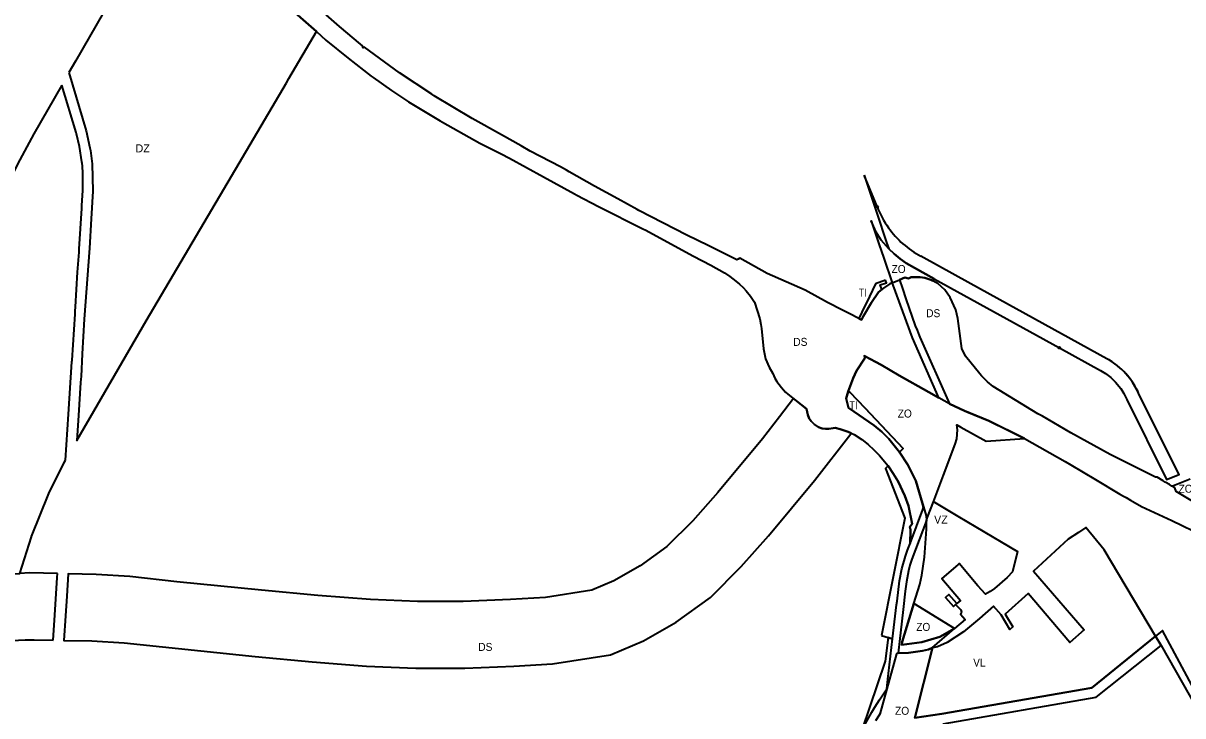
# Model space of a CAD drawing. Extents: x -650276 to -642489, y -1074311 to -1066658.
# Drawn here: x -647860 to -646121, y -1069166 to -1068126 of the extents above; entities that cross this region are included whole.
import ezdxf

# ---------------------------------------------------------------- set-up
doc = ezdxf.new("R2010")
doc.units = 0
doc.header["$LTSCALE"] = 4.8
doc.header["$PDMODE"] = 32
doc.header["$PDSIZE"] = 2.4
for name, color, linetype, lineweight in [('15', 7, 'Continuous', 35), ('24', 7, 'Continuous', 35), ('25', 7, 'Continuous', 35), ('30', 7, 'Continuous', 35), ('34', 7, 'Continuous', 35), ('36', 7, 'Continuous', 35), ('42', 7, 'Continuous', 35)]:
    doc.layers.add(name, color=color, linetype=linetype, lineweight=lineweight)
doc.layers.add('62', color=7, linetype='Continuous')

msp = doc.modelspace()

# ---------------------------------------------------------------- linework, layer by layer
at = {"layer": '15'}
msp.add_lwpolyline([(-646037.99, -1069242.88), (-646107, -1069119.41), (-646150.87, -1069037.64), (-646152.26, -1069038.76), (-646161.484, -1069046.228), (-646153.307, -1069059.947), (-646025.14, -1069285.394)], dxfattribs=at)
at = {"layer": '24'}
msp.add_line((-646578.881, -1068401.54), (-646598.635, -1068354.436), dxfattribs=at)
msp.add_line((-646578.881, -1068401.54), (-646598.635, -1068354.436), dxfattribs=at)
for points in [[(-647618.773, -1067899.914), (-647553.628, -1067999.427), (-647472.338, -1068093.096), (-647419.713, -1068138.871)], [(-646634.37, -1068735.27), (-646622.62, -1068739.32), (-646613.44, -1068743.65), (-646601.86, -1068751.01), (-646592.53, -1068758.66), (-646583.98, -1068766.42), (-646575.28, -1068775.04), (-646562.49, -1068790.69), (-646554.8, -1068801.98), (-646547.68, -1068814.22), (-646537.35, -1068835.56), (-646532.16, -1068850.47), (-646526.64, -1068877.47), (-646530.06, -1068882.16), (-646528.92, -1068886.55), (-646529.44, -1068906.81), (-646510.56, -1068855.86), (-646509.323, -1068852.529), (-646513.27, -1068838.37), (-646521.18, -1068812.95), (-646532.92, -1068788.95), (-646545.32, -1068769.89), (-646561.5, -1068750.22), (-646571.91, -1068739.54), (-646583.49, -1068729.76), (-646622.01, -1068703.3), (-646625.35, -1068689.7), (-646622.68, -1068678.75), (-646615.19, -1068659.11), (-646609.7, -1068647.84), (-646597.4, -1068628.74), (-646596.28, -1068626.52), (-646596.28, -1068626.52), (-646573.14, -1068638.98), (-646545.73, -1068654.81), (-646545.73, -1068654.81), (-646501.64, -1068679.81), (-646486.23, -1068688.54), (-646526.1, -1068598.55), (-646555, -1068519.38), (-646555, -1068519.38), (-646556.22, -1068515.84), (-646559.72, -1068517.29), (-646569.61, -1068524.1), (-646572.02, -1068526.07), (-646577.07, -1068530.2), (-646587.28, -1068545.28), (-646599.75, -1068566.49), (-646602.21, -1068571.5), (-646606.59, -1068569.33), (-646620.94, -1068561.96), (-646625.86, -1068559.47), (-646631.18, -1068556.77), (-646653.21, -1068545.58), (-646686.84, -1068526.89), (-646686.84, -1068526.89), (-646743.69, -1068501.76), (-646785.05, -1068479.12), (-646787.55, -1068480.36), (-646789.49, -1068481.31), (-646832.29, -1068460.04), (-646864.48, -1068444.64), (-646936.47, -1068407.23), (-646938.95, -1068405.8), (-646967.64, -1068390), (-647002.71, -1068371.09), (-647040.77, -1068349.4), (-647044.93, -1068347.08), (-647053.75, -1068342.11), (-647099.2, -1068318.27), (-647112.813, -1068310.564), (-647142.41, -1068293.81), (-647186.26, -1068269.45), (-647243.39, -1068235.26), (-647246.8, -1068233.08), (-647295.47, -1068201.09), (-647347.74, -1068162.54), (-647349.59, -1068163.24), (-647350.6, -1068160.26), (-647353.81, -1068157.67), (-647385.13, -1068131.51), (-647405.026, -1068113.904)], [(-647419.713, -1068138.871), (-647405.71, -1068151.74), (-647372.38, -1068179.01), (-647337.74, -1068205.67), (-647334.62, -1068208.02), (-647307.39, -1068227.44), (-647281.64, -1068244.34), (-647234.11, -1068273.04), (-647230.83, -1068274.93), (-647174.56, -1068306.35), (-647142.788, -1068322.462), (-647130.29, -1068328.8), (-647079.16, -1068357.01), (-647032.91, -1068382.51), (-647029.23, -1068384.46), (-646997.06, -1068401.37), (-646929.56, -1068435.42), (-646927.06, -1068436.66)], [(-646598.635, -1068354.436), (-646579.62, -1068411.29), (-646564.78, -1068455.41), (-646561.544, -1068464.842)], [(-646598.635, -1068354.436), (-646579.62, -1068411.29), (-646564.78, -1068455.41), (-646561.544, -1068464.842)], [(-646927.06, -1068436.66), (-646854.18, -1068475.8), (-646828.2, -1068489.61), (-646807.82, -1068501.17), (-646799.79, -1068506.39), (-646790.66, -1068513.24), (-646785.34, -1068517.77), (-646779.93, -1068522.9), (-646775.44, -1068527.74), (-646768.95, -1068535.8), (-646763.1, -1068545.18), (-646754.92, -1068569.81), (-646753.35, -1068578.6), (-646752.59, -1068584.55), (-646749.35, -1068615.18), (-646746.32, -1068630.23), (-646740.91, -1068642.34), (-646735.62, -1068652.21), (-646732.25, -1068659.06), (-646729.34, -1068663.94), (-646722.6, -1068673.11), (-646716.39, -1068679.8), (-646716.39, -1068679.8), (-646712.93, -1068683), (-646684.7, -1068704.95), (-646682.98, -1068714.07), (-646680.88, -1068719.28), (-646678.08, -1068723.7), (-646673.16, -1068728.69), (-646667.17, -1068732.38), (-646667.17, -1068732.38), (-646661.5, -1068734.35), (-646656.47, -1068735.13), (-646651.21, -1068734.99), (-646645.18, -1068733.91), (-646642.04, -1068733.74), (-646634.37, -1068735.27)], [(-646561.544, -1068464.842), (-646553.677, -1068472.283), (-646544.525, -1068479.79), (-646535.245, -1068486.342), (-646523.105, -1068493.54), (-646493.511, -1068509.855), (-646305.678, -1068613.404)], [(-646561.544, -1068464.842), (-646553.677, -1068472.283), (-646544.525, -1068479.79), (-646535.245, -1068486.342), (-646523.105, -1068493.54), (-646493.511, -1068509.855), (-646305.678, -1068613.404)], [(-646234.342, -1068629.893), (-646234.342, -1068629.892), (-646438.626, -1068517.274), (-646513.45, -1068476.025), (-646513.567, -1068475.963)], [(-646234.342, -1068629.893), (-646234.342, -1068629.892), (-646438.626, -1068517.274), (-646513.45, -1068476.025), (-646513.567, -1068475.963)], [(-646337.93, -1068712.4), (-646404.83, -1068671.52), (-646413.45, -1068664.71), (-646422.32, -1068655.58), (-646425.11, -1068652.37), (-646446.54, -1068626.14), (-646451.82, -1068614.31), (-646458.03, -1068569.26), (-646461.14, -1068556.34), (-646469.51, -1068538.15), (-646477.41, -1068526.45), (-646487.92, -1068516.87), (-646498.48, -1068511.26), (-646507.4, -1068508.45), (-646514.39, -1068507.56), (-646528.18, -1068507.58), (-646531.9, -1068509.25), (-646537.71, -1068508.16), (-646545.57, -1068511.42), (-646541.06, -1068524.58), (-646535.84, -1068539.8), (-646521.81, -1068580.69), (-646519.14, -1068587.06), (-646516.07, -1068595.08), (-646515.09, -1068597.29), (-646470.65, -1068697.38), (-646448.02, -1068707.99), (-646444.51, -1068709.64), (-646411.3, -1068723.11), (-646380.94, -1068737.81), (-646357.87, -1068749.64), (-646297.08, -1068783.8), (-646288.37, -1068789.04), (-646251.73, -1068811.04), (-646214.92, -1068832.85), (-646208.7, -1068836.39), (-646205.48, -1068838.23), (-646199.24, -1068841.79), (-646195.52, -1068843.92), (-646182.57, -1068851.3)], [(-646305.678, -1068613.404), (-646243.997, -1068647.407), (-646236.707, -1068651.891), (-646228.691, -1068658.051), (-646221.348, -1068665.144), (-646213.659, -1068674.696), (-646209.179, -1068681.795), (-646204.654, -1068690.937), (-646145.083, -1068810.83), (-646126.317, -1068803.654), (-646186.371, -1068682.825)], [(-646305.678, -1068613.404), (-646243.997, -1068647.407), (-646236.707, -1068651.891), (-646228.691, -1068658.051)], [(-646228.691, -1068658.051), (-646221.348, -1068665.144), (-646213.659, -1068674.696), (-646209.179, -1068681.795), (-646204.654, -1068690.937), (-646145.083, -1068810.83), (-646126.317, -1068803.654), (-646186.371, -1068682.825)], [(-646075.56, -1068861.95), (-646130.68, -1068829.21), (-646132.62, -1068823.54), (-646136.99, -1068820.88), (-646140.73, -1068818.61), (-646146.85, -1068814.88), (-646150.26, -1068812.81), (-646159.1, -1068807.43), (-646161.45, -1068807.54), (-646229.44, -1068773.53), (-646288.59, -1068740.88), (-646331.26, -1068716.25), (-646337.93, -1068712.4)], [(-646182.57, -1068851.3), (-646137.23, -1068872.6), (-646089.63, -1068895.5)], [(-646505.17, -1068872.78), (-646526.81, -1068930.69), (-646530.08, -1068939.43), (-646532.13, -1068948), (-646535.13, -1068964.38), (-646537.02, -1068978.44), (-646539.77, -1069006.25), (-646547.412, -1069071.71), (-646532, -1069071)], [(-646505.17, -1068872.78), (-646526.81, -1068930.69), (-646530.08, -1068939.43), (-646532.13, -1068948), (-646535.13, -1068964.38), (-646537.02, -1068978.44), (-646539.77, -1069006.25)], [(-646524, -1068997), (-646514.91, -1068968.48), (-646514.91, -1068968.48), (-646512.07, -1068954.68), (-646507.91, -1068927.47), (-646505.12, -1068885.31), (-646505.17, -1068872.78)], [(-646524, -1068997), (-646514.91, -1068968.48), (-646514.91, -1068968.48), (-646512.07, -1068954.68), (-646507.91, -1068927.47), (-646505.12, -1068885.31), (-646505.17, -1068872.78)], [(-647808.28, -1068952.066), (-647850.043, -1068951.098), (-647864.531, -1068951.823)], [(-647814.401, -1069052.246), (-647812.34, -1069014.54), (-647808.67, -1068958.06), (-647808.28, -1068952.066)], [(-646539.77, -1069006.25), (-646539.77, -1069006.25), (-646547.412, -1069071.71)], [(-646462.98, -1069034.61), (-646485, -1069047), (-646512, -1069055), (-646542, -1069059), (-646541.71, -1069054.76), (-646524, -1068997)], [(-646512, -1069055), (-646542, -1069059), (-646541.71, -1069054.76), (-646524, -1068997)], [(-646547.412, -1069071.71), (-646532, -1069071), (-646511, -1069068), (-646502, -1069066), (-646496.317, -1069063.61), (-646462.98, -1069034.61)], [(-646532, -1069071), (-646511, -1069068), (-646502, -1069066), (-646496.317, -1069063.61), (-646462.98, -1069034.61), (-646485, -1069047), (-646512, -1069055)], [(-648040.705, -1069069.547), (-648039.666, -1069069.279), (-647948.18, -1069057.276), (-647886.615, -1069053.052), (-647856.541, -1069051.548), (-647848.615, -1069051.679), (-647842.888, -1069051.774), (-647814.401, -1069052.246)]]:
    msp.add_lwpolyline(points, dxfattribs=at)
for points in [[(-646934.465, -1068940.759), (-646973.61, -1068963.135), (-647006.63, -1068977.08), (-647076.422, -1068988.18), (-647128.674, -1068991.167), (-647199.672, -1068994.255), (-647268.348, -1068994.255), (-647338.816, -1068991.19), (-647417.895, -1068984.986), (-647502.412, -1068977.157), (-647629.424, -1068964.608), (-647699.561, -1068956.635), (-647749.978, -1068953.416), (-647792.01, -1068952.442), (-647794.21, -1068986.12), (-647796.13, -1069015.57), (-647798.631, -1069052.508), (-647756.441, -1069053.207), (-647708.401, -1069056.275), (-647511.94, -1069076.703), (-647426.417, -1069084.624), (-647344.902, -1069091.02), (-647270.522, -1069094.255), (-647197.498, -1069094.255), (-647123.648, -1069091.043), (-647065.688, -1069087.73), (-646978.92, -1069073.93), (-646929.186, -1069052.925), (-646880.163, -1069024.903), (-646829.104, -1068987.917), (-646782.784, -1068941.581), (-646741.85, -1068895.719), (-646673.05, -1068812.491), (-646618.655, -1068742.359), (-646617.991, -1068741.503), (-646622.62, -1068739.32), (-646634.37, -1068735.27), (-646642.04, -1068733.74), (-646645.18, -1068733.91), (-646651.21, -1068734.99), (-646656.47, -1068735.13), (-646661.5, -1068734.35), (-646667.17, -1068732.38), (-646673.16, -1068728.69), (-646678.08, -1068723.7), (-646680.88, -1068719.28), (-646682.98, -1068714.07), (-646684.7, -1068704.95), (-646704.316, -1068689.698), (-646725.374, -1068716.786), (-646751.116, -1068749.975), (-646817.718, -1068830.545), (-646855.506, -1068872.883), (-646894.206, -1068911.595)], [(-646582.46, -1069152.81), (-646575.4, -1069141.46), (-646564.54, -1069125.08), (-646562.35, -1069106.21), (-646561.88, -1069102.18), (-646555.84, -1069050.22), (-646555.84, -1069050.22), (-646559.8, -1069048.98), (-646562.61, -1069048.08), (-646566.82, -1069083.62), (-646601.82, -1069187.25), (-646586.97, -1069160.06), (-646585.42, -1069157.56), (-646583.89, -1069155.1), (-646582.46, -1069152.81)]]:
    msp.add_lwpolyline(points, close=True, dxfattribs=at)
for centre, radius, start, end in [((-646447.332, -1068351.964), 140.58, 200.6496, 215.36619), ((-646447.332, -1068351.964), 140.58, 200.64975, 215.36619), ((-646447.332, -1068351.964), 140.58, 215.36631, 241.891), ((-646447.332, -1068351.964), 140.58, 215.36642, 241.891), ((-646287.447, -1068726.224), 110, 23.23727, 61.13296), ((-646287.447, -1068726.224), 110, 57.43148, 61.13296), ((-646287.447, -1068726.224), 110, 23.23727, 57.43149)]:
    msp.add_arc(centre, radius, start, end, dxfattribs=at)
for p in [(-646578.881, -1068401.54), (-646305.678, -1068613.404)]:
    msp.add_point(p, dxfattribs=at)
at = {"layer": '25'}
for points in [[(-647464.94, -1068215.752), (-647461.188, -1068209.373), (-647419.713, -1068138.871), (-647472.338, -1068093.096), (-647553.628, -1067999.427), (-647618.773, -1067899.914), (-647685.819, -1068016.861)], [(-647685.819, -1068016.861), (-647781.346, -1068183.485), (-647791.055, -1068200.507)], [(-647791.055, -1068200.507), (-647765.22, -1068287.94), (-647759.412, -1068313.436)], [(-647801.797, -1068219.34), (-647843.6, -1068292.629), (-647868.214, -1068337.803), (-647914.339, -1068432.512), (-647946.187, -1068510.254), (-647971.074, -1068581.98), (-647997.27, -1068674.747), (-648011.775, -1068739.718), (-648023.914, -1068809.332), (-648030.73, -1068861.213), (-648038.596, -1068968.281)], [(-647771.413, -1068334.626), (-647774.94, -1068311.47), (-647779.55, -1068292.23), (-647780.07, -1068290.53), (-647801.797, -1068219.34)], [(-647768.02, -1068570.36), (-647770.94, -1068622.47), (-647772.85, -1068656.41), (-647773.08, -1068660.57), (-647773.4, -1068665.71), (-647776.5, -1068714.8), (-647778.95, -1068752.433), (-647675.054, -1068572.919), (-647535.844, -1068336.279), (-647464.94, -1068215.752)], [(-647759.412, -1068313.436), (-647758.45, -1068317.66), (-647756.09, -1068337.61), (-647754.99, -1068378.21), (-647757.41, -1068419.98), (-647760.22, -1068463.96), (-647768.02, -1068570.36)], [(-647796.173, -1068782.191), (-647791.77, -1068713.23), (-647786.47, -1068634.37), (-647786.32, -1068632.19), (-647781.85, -1068562.97), (-647781.55, -1068558.38), (-647781.13, -1068551.88), (-647778.24, -1068499.95), (-647775.82, -1068469.74), (-647775.52, -1068464.97), (-647771.74, -1068404.5), (-647771.47, -1068400.07), (-647770.12, -1068377.5), (-647769.92, -1068352.1), (-647770.81, -1068340.29), (-647771.05, -1068337.01), (-647771.413, -1068334.626)], [(-647846.989, -1068896.545), (-647820.883, -1068832.117), (-647797.632, -1068784.713), (-647796.173, -1068782.191)], [(-647958.168, -1068957.73), (-647895.901, -1068953.392), (-647864.531, -1068951.823), (-647847.197, -1068897.199), (-647847.034, -1068896.687), (-647846.989, -1068896.545)]]:
    msp.add_lwpolyline(points, dxfattribs=at)
at = {"layer": '30'}
msp.add_line((-646583.49, -1068729.76), (-646571.91, -1068739.54), dxfattribs=at)
for points in [[(-646566.33, -1068512.04), (-646581.64, -1068517.24), (-646590.31, -1068536.69), (-646602.01, -1068560.15), (-646606.59, -1068569.33)], [(-646587.28, -1068545.28), (-646577.07, -1068530.2), (-646572.02, -1068526.07), (-646574.48, -1068518.75), (-646565.04, -1068515.86), (-646566.33, -1068512.04)], [(-646599.75, -1068566.49), (-646587.28, -1068545.28), (-646587.28, -1068545.28)], [(-646606.59, -1068569.33), (-646602.21, -1068571.5), (-646599.75, -1068566.49)], [(-646571.91, -1068739.54), (-646561.5, -1068750.22), (-646545.32, -1068769.89), (-646539.78, -1068764.65), (-646596.93, -1068704.15), (-646619.74, -1068680.15), (-646622.68, -1068678.75), (-646625.35, -1068689.7)], [(-646625.35, -1068689.7), (-646622.01, -1068703.3), (-646583.49, -1068729.76)], [(-646562.49, -1068790.69), (-646566.34, -1068794.32), (-646537.3, -1068868.95), (-646572.42, -1069044.94)], [(-646526.64, -1068877.47), (-646532.16, -1068850.47), (-646537.35, -1068835.56), (-646547.68, -1068814.22), (-646554.8, -1068801.98), (-646562.49, -1068790.69)], [(-646529.44, -1068906.81), (-646528.92, -1068886.55), (-646530.06, -1068882.16), (-646526.64, -1068877.47)], [(-646555.84, -1069050.22), (-646550.89, -1069007.7), (-646549.81, -1068998.88), (-646549.17, -1068993.71), (-646545.42, -1068963.3), (-646542.16, -1068945.12), (-646536.54, -1068925.95), (-646533.28, -1068917.17), (-646529.44, -1068906.81)], [(-646572.42, -1069044.94), (-646562.61, -1069048.08), (-646559.8, -1069048.98), (-646555.84, -1069050.22)]]:
    msp.add_lwpolyline(points, dxfattribs=at)
at = {"layer": '34'}
msp.add_lwpolyline([(-646161.484, -1069046.228), (-646238.632, -1068916.799), (-646266.118, -1068883.048), (-646277.268, -1068890.446), (-646292.75, -1068900.72), (-646344.49, -1068948.736), (-646268.528, -1069036.82), (-646290.099, -1069055.423), (-646352.71, -1068981.82), (-646386.936, -1069012.936), (-646375.346, -1069032.07), (-646379.973, -1069035.889), (-646393.09, -1069014.234), (-646404.269, -1069001.033), (-646425.52, -1069019.41), (-646449.418, -1069039.804), (-646474.13, -1069055.83), (-646488.537, -1069062.169), (-646495.89, -1069063.531), (-646522.35, -1069168.648), (-646482.211, -1069162.813), (-646256.824, -1069123.414)], close=True, dxfattribs=at)
at = {"layer": '36'}
msp.add_lwpolyline([(-646512.07, -1068954.68), (-646507.91, -1068927.47), (-646505.12, -1068885.31), (-646505.17, -1068872.78), (-646503.24, -1068867.61), (-646494.52, -1068844.29), (-646492.73, -1068845.01), (-646457.86, -1068865.8), (-646430.86, -1068881.89), (-646368.3, -1068919.19), (-646376.02, -1068949.34), (-646383.86, -1068958.24), (-646403.13, -1068974.41), (-646409.67, -1068979.3), (-646416.71, -1068983.21), (-646427.77, -1068970.39), (-646455.78, -1068936.87), (-646458.21, -1068938.99), (-646482.2, -1068959.52), (-646454.21, -1068992.73), (-646459.25, -1068996.98), (-646471.24, -1068983.41), (-646476.35, -1068987.98), (-646464.24, -1069001.49), (-646461.29, -1068998.81), (-646453.48, -1069006.75), (-646452.37, -1069010.01), (-646453.88, -1069013.1), (-646447.2, -1069020.9), (-646462.98, -1069034.61), (-646524, -1068997), (-646514.91, -1068968.48), (-646514.91, -1068968.48)], close=True, dxfattribs=at)
at = {"layer": '42'}
for points in [[(-646561.544, -1068464.842), (-646572.984, -1068451.81), (-646580.625, -1068439.803), (-646588.07, -1068422.96), (-646576.4, -1068457.27), (-646568.87, -1068479.14), (-646556.22, -1068515.84), (-646545.57, -1068511.42), (-646537.71, -1068508.16)], [(-646523.105, -1068493.54), (-646535.245, -1068486.342), (-646544.525, -1068479.79), (-646553.677, -1068472.283), (-646561.544, -1068464.842)], [(-646537.71, -1068508.16), (-646531.9, -1068509.25), (-646528.18, -1068507.58), (-646514.39, -1068507.56), (-646507.4, -1068508.45), (-646498.48, -1068511.26), (-646495.416, -1068512.888), (-646493.511, -1068509.855), (-646523.105, -1068493.54)], [(-646075.56, -1068861.95), (-646130.68, -1068829.21), (-646132.62, -1068823.54), (-646136.99, -1068820.88), (-646109.35, -1068810.23)], [(-646479.84, -1069177.626), (-646250.409, -1069137.52), (-646153.307, -1069059.947), (-646161.484, -1069046.228), (-646256.824, -1069123.414), (-646482.211, -1069162.813), (-646522.35, -1069168.648), (-646495.89, -1069063.531), (-646496.317, -1069063.61), (-646496.317, -1069063.61), (-646502, -1069066), (-646511, -1069068), (-646532, -1069071), (-646547.412, -1069071.71), (-646549.91, -1069072.542), (-646564.54, -1069125.08), (-646564.605, -1069125.271), (-646574.978, -1069163.017), (-646574.978, -1069163.017), (-646574.33, -1069162.04), (-646575.87, -1069164.54), (-646581.29, -1069173.32)]]:
    msp.add_lwpolyline(points, dxfattribs=at)
for points in [[(-646609.7, -1068647.84), (-646615.19, -1068659.11), (-646622.68, -1068678.75), (-646619.74, -1068680.15), (-646596.93, -1068704.15), (-646539.78, -1068764.65), (-646545.32, -1068769.89), (-646532.92, -1068788.95), (-646521.18, -1068812.95), (-646513.27, -1068838.37), (-646505.69, -1068865.56), (-646505.17, -1068872.78), (-646503.24, -1068867.61), (-646494.52, -1068844.29), (-646479.45, -1068804.37), (-646461.92, -1068757.93), (-646459.59, -1068750.19), (-646458.57, -1068736.31), (-646459.54, -1068728.94), (-646453.51, -1068732.3), (-646415.3, -1068753.62), (-646357.87, -1068749.64), (-646411.3, -1068723.11), (-646448.02, -1068707.99), (-646470.65, -1068697.38), (-646486.23, -1068688.54), (-646501.64, -1068679.81), (-646545.73, -1068654.81), (-646573.14, -1068638.98), (-646598.59, -1068625.34), (-646597.4, -1068628.74)], [(-646541.71, -1069054.76), (-646542, -1069059), (-646512, -1069055), (-646485, -1069047), (-646462.98, -1069034.61), (-646524, -1068997)]]:
    msp.add_lwpolyline(points, close=True, dxfattribs=at)

# ---------------------------------------------------------------- texts
at = {"layer": '62'}
for s, p in [('DZ', (-647691.118, -1068320.225)), ('VZ', (-646493.598, -1068877.069))]:
    msp.add_text(s, height=12, dxfattribs=at).set_placement(p)
for s, width, p in [('ZO', 0.95, (-646557.423, -1068501.188)), ('TI', 0.85, (-646606.476, -1068536.535)), ('DS', 0.95, (-646505.476, -1068567.535)), ('DS', 0.95, (-646704.709, -1068610.535)), ('TI', 0.85, (-646620.476, -1068705.535)), ('ZO', 0.95, (-646548.118, -1068718.035)), ('ZO', 0.95, (-646127.027, -1068830.859)), ('ZO', 0.95, (-646520.423, -1069038.188)), ('DS', 0.95, (-647177.118, -1069068.225)), ('VL', 0.95, (-646434.928, -1069091.6)), ('ZO', 0.95, (-646552.118, -1069164.035))]:
    msp.add_text(s, height=12, dxfattribs=dict(at, width=width)).set_placement(p)

doc.saveas('drawing.dxf')
